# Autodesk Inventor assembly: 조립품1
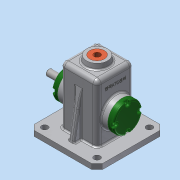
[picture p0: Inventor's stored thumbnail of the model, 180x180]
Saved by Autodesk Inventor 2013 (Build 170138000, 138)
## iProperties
Created: 2016-02
Part Number: 조립품1
Document SubType Name: Assembly
Designer: dgall
Author: dgall
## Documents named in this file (7)
- C:\Users\dgall\Desktop\460211V1001\조립품1.iam
- C:\Users\dgall\Desktop\460211V1001\460211V1001 양종훈.ipt
- C:\Users\dgall\Desktop\460211V1001\부시.ipt
- C:\Users\dgall\Desktop\460211V1001\앞커버.ipt
- C:\Users\dgall\Desktop\460211V1001\뒤커버.ipt
- C:\Users\dgall\Desktop\460211V1001\베어링 12 x 32 x 10.ipt
- C:\Users\dgall\Desktop\460211V1001\편심축.ipt
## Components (1 placed, 1 different names)
1. 460211V1001 양종훈:1
